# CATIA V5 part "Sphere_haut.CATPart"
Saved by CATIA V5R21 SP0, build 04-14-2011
Part number: Sphere_haut
Bounding box of the stored display mesh (mm): x -13 to 13, y -16 to 16, z -11.25 to 3
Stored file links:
  D:\FRANCE\Stage\CAO\CAO final\3D impression\Sphere_haut.CATPart
  D:\FRANCE\Stage\CAO\CAO final\3D impression\Sphere_assemblage.CATProduct
  D:\FRANCE\Stage\CAO\CAO final\3D impression\Sphere_bas_1.CATPart
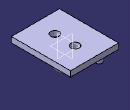
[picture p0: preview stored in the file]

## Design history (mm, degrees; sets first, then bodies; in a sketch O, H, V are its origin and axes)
External parameters (linked from other documents)
  External.Radius = 6 mm
  External.Length = 5.25 mm
Body1 (main body)
  Sketch1 on yz-plane, origin (0, 0, 0), H (0, 1, 0), V (0, 0, 1)
    arc A1 centre (0, -5.25) radius 6 from (0, -11.25) to (2.9047, 0) ccw
    point P1 (0, -5.25)
    line L1 (0, -11.25) -> (0, 0)
    point P3 (2.9047, 0)
    line L2 (2.9047, 0) -> (0, 0)
    radius A1 = 6 {= External.Radius}
    distance P1 H = 5.25 {= External.Length}
    coincidence: P1 V, L1 V, L2 H, P3 H
  Shaft1: profile Sketch1, axis Sketch1.L1, angle 360
  Sketch2 on face of Shaft1 from Sketch1.L2, origin (0, 0, 0), H (1, 0, 0), V (0, 1, 0)
    point P1 (0, -16)
    line L1 (0, -16) -> (0, 16)
    line L2 (0, 16) -> (-13, 16)
    line L3 (-13, 16) -> (-13, -16)
    line L4 (-13, -16) -> (0, -16)
    length L4 = 13
    length L3 = 32
    coincidence: P1 V, L1 V
    vertical: L1 V, L3 V
    horizontal: L2 H, L4 H
    symmetry: L4 L2 H
  Pad1: profile Sketch2, direction (0, 0, 1), length 3
  Mirror1: of Pad1, about yz-plane
  Sketch3 on face of Mirror1, origin (0, 0, 0), H (1, 0, 0), V (0, -1, 0)
    circle A1 centre (-5, 13.5) radius 1.5
    point P1 (-5, 13.5)
    reference projected line E1 (-13, 16) -> (0, 16) from edge [face of Mirror1 | face of Mirror1]
    radius A1 = 1.5
    distance P1 V = 5
    distance P1 E1 = 2.5
  Pad2: profile Sketch3, direction (0, 0, -1), length 1
  Sketch4 on face of Mirror1, origin (0, 0, 0), H (1, 0, 0), V (0, -1, 0)
    circle A1 centre (-5, -13.5) radius 1.5
    point P1 (-5, -13.5)
    reference projected line E1 (0, -16) -> (-13, -16) from edge [face of Mirror1 | face of Mirror1]
    radius A1 = 1.5
    distance P1 E1 = 2.5
    distance P1 V = 5
  Pad3: profile Sketch4, direction (0, 0, -1), length 3
  Sketch5 on face of Mirror1, origin (0.7028, 8.1776, 3), H (1, 0, 0), V (0, 1, 0)
    point P1 (-0.7028, -2.6776)
    reference projected line E1 (-0.7028, 7.8224) -> (-13.7028, 7.8224) from edge [face of Mirror1 | face of Mirror1]
    reference projected line E2 (-13.7028, 7.8224) -> (-13.7028, -24.1776) from edge [face of Pad1 from Sketch2.L3 | face of Mirror1]
    distance P1 E1 = 10.5
    distance P1 E2 = 13
  Hole1: placed by Sketch5, at (0, 5.5, 3) direction (0, 0, -1), diameter 4.5, up to face of Mirror1
  Mirror2: of Hole1, about zx-plane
